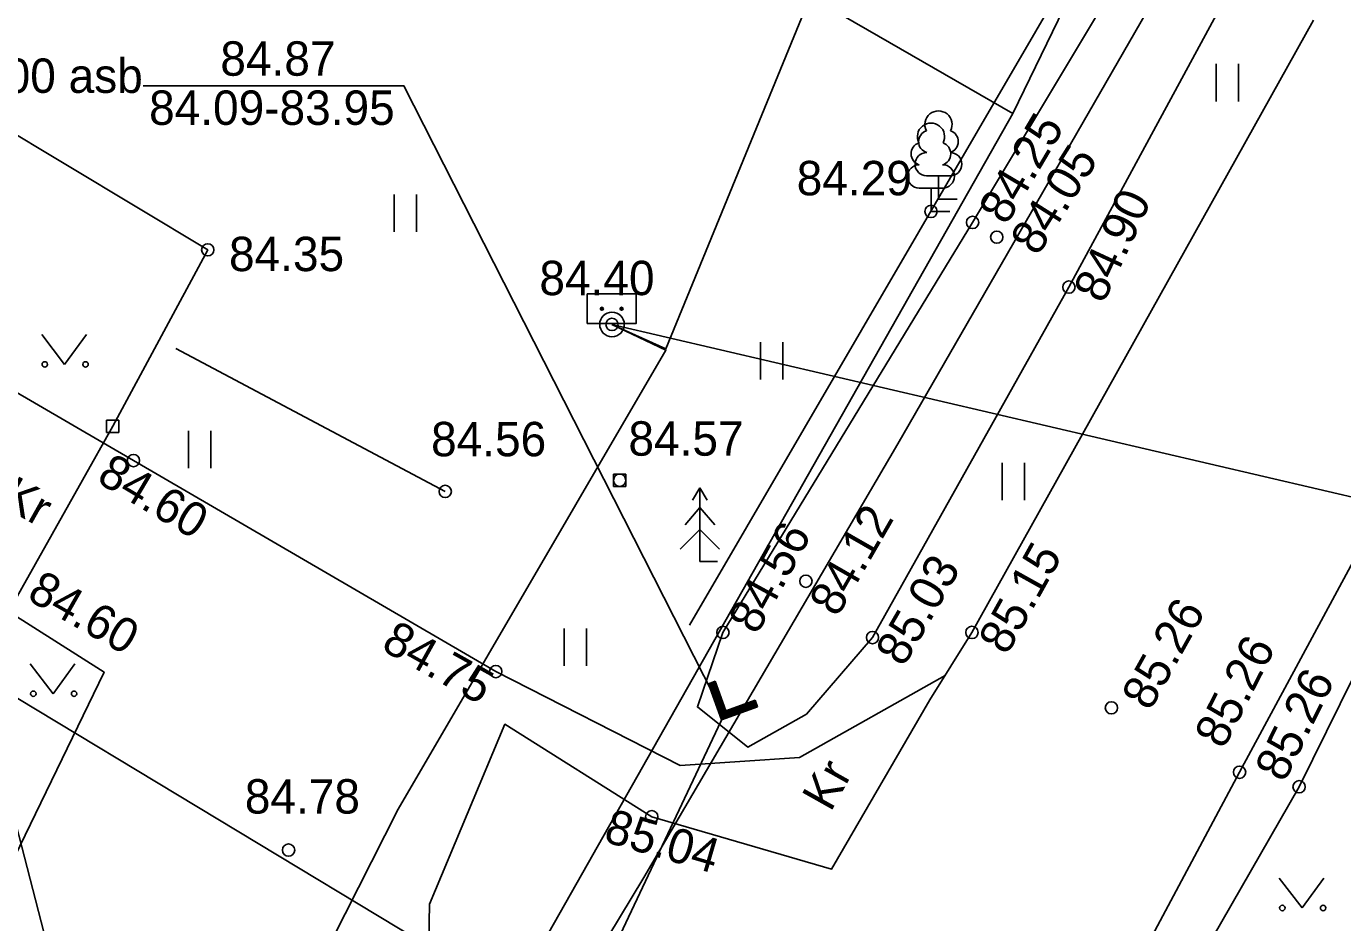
# Model space of a CAD drawing. Extents: x 648748 to 649126, y 6457789 to 6458252.
# Drawn here: x 648884.43 to 648911.21, y 6458173.84 to 6458192.08 of the extents above; entities that cross this region are included whole.
import ezdxf

# ---------------------------------------------------------------- set-up
doc = ezdxf.new("R2010")
doc.units = 0
for name, color, linetype in [('AED', 7, 'Continuous'), ('HALJASTUS', 7, 'Continuous'), ('KORGUS-EH2000', 7, 'Continuous'), ('KTRASS', 7, 'Continuous'), ('MPOHULIIN', 7, 'Continuous'), ('PIIR', 7, 'Continuous'), ('POST', 7, 'Continuous'), ('PUU', 7, 'Continuous'), ('SIOHULIIN', 7, 'Continuous'), ('SIRAJATIS', 7, 'Continuous'), ('SITRASS', 7, 'Continuous'), ('TEE', 7, 'Continuous'), ('TRUUP', 7, 'Continuous'), ('VEEKOGU', 7, 'Continuous')]:
    doc.layers.add(name, color=color, linetype=linetype)

msp = doc.modelspace()

# ---------------------------------------------------------------- linework, layer by layer
at = {"layer": 'AED'}
for p, q in [((648886.06, 6458184.069), (648886.06, 6458183.819)), ((648886.06, 6458184.069), (648886.31, 6458184.069)), ((648886.31, 6458184.069), (648886.31, 6458183.819)), ((648886.06, 6458183.819), (648886.31, 6458183.819)), ((648896.374, 6458182.97), (648896.374, 6458182.72)), ((648896.374, 6458182.97), (648896.624, 6458182.97)), ((648896.624, 6458182.97), (648896.624, 6458182.72)), ((648896.374, 6458182.72), (648896.624, 6458182.72))]:
    msp.add_line(p, q, dxfattribs=at)
msp.add_lwpolyline([(648883.709, 6458179.555), (648886.185, 6458183.944), (648888.119, 6458187.534), (648883.783, 6458190.14)], dxfattribs=at)
at = {"layer": 'HALJASTUS'}
for p, q in [((648908.637, 6458191.316), (648908.637, 6458190.555)), ((648909.092, 6458191.316), (648909.092, 6458190.555)), ((648891.91, 6458188.663), (648891.91, 6458187.902)), ((648892.365, 6458188.663), (648892.365, 6458187.902)), ((648884.741, 6458185.811), (648885.204, 6458185.204)), ((648885.204, 6458185.204), (648885.65, 6458185.811)), ((648892.951, 6458182.619), (648887.471, 6458185.525)), ((648899.366, 6458185.659), (648899.366, 6458184.898)), ((648899.821, 6458185.659), (648899.821, 6458184.898)), ((648887.727, 6458183.855), (648887.727, 6458183.094)), ((648888.182, 6458183.855), (648888.182, 6458183.094)), ((648904.281, 6458183.199), (648904.281, 6458182.438)), ((648904.736, 6458183.199), (648904.736, 6458182.438)), ((648895.368, 6458179.832), (648895.368, 6458179.071)), ((648895.823, 6458179.832), (648895.823, 6458179.071)), ((648884.508, 6458179.11), (648884.971, 6458178.503)), ((648884.971, 6458178.503), (648885.417, 6458179.11)), ((648909.918, 6458174.75), (648910.382, 6458174.143)), ((648910.382, 6458174.143), (648910.827, 6458174.75))]:
    msp.add_line(p, q, dxfattribs=at)
msp.add_lwpolyline([(648914.508, 6458217.558), (648916.03, 6458214.515), (648914.704, 6458209.998), (648909.63, 6458199.994), (648897.923, 6458179.895)], dxfattribs=at)
for centre in [(648884.803, 6458185.204), (648885.632, 6458185.204), (648884.57, 6458178.503), (648885.399, 6458178.503), (648909.981, 6458174.143), (648910.81, 6458174.143)]:
    msp.add_circle(centre, 0.055, dxfattribs=at)
at = {"layer": 'KORGUS-EH2000'}
for centre in [(648902.833, 6458188.317), (648903.68, 6458188.093), (648904.171, 6458187.792), (648888.119, 6458187.534), (648905.64, 6458186.776), (648896.343, 6458186.017), (648886.607, 6458183.247), (648896.499, 6458182.845), (648892.951, 6458182.619), (648900.287, 6458180.792), (648898.6, 6458179.75), (648901.643, 6458179.646), (648903.667, 6458179.751), (648893.979, 6458178.952), (648906.503, 6458178.216), (648909.112, 6458176.906), (648910.322, 6458176.61), (648897.151, 6458176.001), (648889.763, 6458175.322)]:
    msp.add_circle(centre, 0.125, dxfattribs=at)
at = {"layer": 'KTRASS'}
msp.add_line((648918.483, 6458157.779), (648878.199, 6458182.051), dxfattribs=at)
at = {"layer": 'MPOHULIIN'}
msp.add_lwpolyline([(648879.733, 6458193.241), (648887.677, 6458162.414), (648896.676, 6458127.492), (648901.112, 6458110.279), (648910.288, 6458074.678)], dxfattribs=at)
at = {"layer": 'PIIR'}
for p, q in [((648919.27, 6458220.73), (648904.5, 6458190.31)), ((648882.169, 6458203.173), (648904.5, 6458190.31)), ((648904.5, 6458190.31), (648875.65, 6458139.39))]:
    msp.add_line(p, q, dxfattribs=at)
at = {"layer": 'POST'}
msp.add_circle((648896.343, 6458186.017), 0.25, dxfattribs=at)
at = {"layer": 'PUU'}
for p, q in [((648903.224, 6458189.039), (648902.744, 6458189.039)), ((648902.984, 6458188.564), (648902.984, 6458189.039)), ((648903.073, 6458188.792), (648902.593, 6458188.792)), ((648902.833, 6458188.317), (648902.833, 6458188.792)), ((648903.364, 6458188.564), (648902.984, 6458188.564)), ((648903.213, 6458188.317), (648902.833, 6458188.317)), ((648898.132, 6458182.691), (648897.982, 6458182.441)), ((648898.282, 6458182.441), (648898.132, 6458182.691)), ((648898.132, 6458182.691), (648898.132, 6458181.191)), ((648898.132, 6458182.291), (648897.832, 6458181.941)), ((648898.432, 6458181.941), (648898.132, 6458182.291)), ((648898.132, 6458181.841), (648897.732, 6458181.441)), ((648898.532, 6458181.441), (648898.132, 6458181.841)), ((648898.492, 6458181.191), (648898.132, 6458181.191))]:
    msp.add_line(p, q, dxfattribs=at)
for centre, radius, start, end in [((648902.984, 6458190.084), 0.277, 332.58, 207.42), ((648902.833, 6458189.837), 0.277, 332.58, 207.42), ((648902.814, 6458189.737), 0.233, 109.022, 253.142), ((648903.154, 6458189.737), 0.233, 286.851, 70.986), ((648902.662, 6458189.489), 0.233, 109.022, 253.142), ((648903.003, 6458189.489), 0.233, 286.851, 70.986), ((648902.747, 6458189.277), 0.238, 90.002, 269.395), ((648903.222, 6458189.277), 0.238, 270.605, 89.998), ((648902.595, 6458189.029), 0.238, 90.002, 269.395), ((648903.07, 6458189.029), 0.238, 270.605, 89.998)]:
    msp.add_arc(centre, radius, start, end, dxfattribs=at)
at = {"layer": 'SIOHULIIN'}
msp.add_line((648896.343, 6458186.017), (648938.076, 6458176.279), dxfattribs=at)
at = {"layer": 'SIRAJATIS'}
msp.add_lwpolyline([(648895.838, 6458186.636), (648896.838, 6458186.636), (648896.838, 6458186.036), (648895.838, 6458186.036)], close=True, dxfattribs=at)
for centre, radius in [((648896.138, 6458186.336), 0.0304), ((648896.138, 6458186.336), 0.029), ((648896.138, 6458186.336), 0.0277), ((648896.138, 6458186.336), 0.0263), ((648896.138, 6458186.336), 0.0249), ((648896.138, 6458186.336), 0.0236), ((648896.138, 6458186.336), 0.0222), ((648896.138, 6458186.336), 0.0209), ((648896.138, 6458186.336), 0.0195), ((648896.138, 6458186.336), 0.0181), ((648896.138, 6458186.336), 0.0168), ((648896.138, 6458186.336), 0.0154), ((648896.138, 6458186.336), 0.014), ((648896.138, 6458186.336), 0.0127), ((648896.138, 6458186.336), 0.0113), ((648896.138, 6458186.336), 0.00996), ((648896.138, 6458186.336), 0.0086), ((648896.138, 6458186.336), 0.00724), ((648896.138, 6458186.336), 0.00587), ((648896.138, 6458186.336), 0.00451), ((648896.138, 6458186.336), 0.00315), ((648896.138, 6458186.336), 0.00179), ((648896.138, 6458186.336), 0.000426), ((648896.538, 6458186.336), 0.0304), ((648896.538, 6458186.336), 0.029), ((648896.538, 6458186.336), 0.0277), ((648896.538, 6458186.336), 0.0263), ((648896.538, 6458186.336), 0.0249), ((648896.538, 6458186.336), 0.0236), ((648896.538, 6458186.336), 0.0222), ((648896.538, 6458186.336), 0.0209), ((648896.538, 6458186.336), 0.0195), ((648896.538, 6458186.336), 0.0181), ((648896.538, 6458186.336), 0.0168), ((648896.538, 6458186.336), 0.0154), ((648896.538, 6458186.336), 0.014), ((648896.538, 6458186.336), 0.0127), ((648896.538, 6458186.336), 0.0113), ((648896.538, 6458186.336), 0.00996), ((648896.538, 6458186.336), 0.0086), ((648896.538, 6458186.336), 0.00724), ((648896.538, 6458186.336), 0.00587), ((648896.538, 6458186.336), 0.00451), ((648896.538, 6458186.336), 0.00315), ((648896.538, 6458186.336), 0.00179), ((648896.538, 6458186.336), 0.000426)]:
    msp.add_circle(centre, radius, dxfattribs=at)
at = {"layer": 'SITRASS'}
for points in [[(648929.925, 6458240.085), (648929.233, 6458238.833), (648926.729, 6458233.327), (648923.21, 6458225.506), (648918.966, 6458215.361), (648917.027, 6458210.342), (648911.341, 6458199.533), (648902.157, 6458183.584), (648896.992, 6458174.764), (648890.118, 6458163.377), (648888.523, 6458160), (648880.878, 6458146.779), (648876.372, 6458138.998), (648873.186, 6458136.533), (648872.398, 6458135.159), (648870.194, 6458131.921), (648868.778, 6458129.583), (648863.975, 6458121.708)], [(648920.046, 6458238.741), (648918.974, 6458235.501), (648918.374, 6458231.362), (648916.343, 6458227.563), (648914.757, 6458225.445), (648913.89, 6458223.662), (648910.648, 6458217.515), (648906.266, 6458207.122), (648902.537, 6458197.956), (648897.439, 6458185.518), (648896.343, 6458186.017)], [(648896.343, 6458186.017), (648897.439, 6458185.494), (648891.994, 6458176.157), (648887.134, 6458166.562), (648880.865, 6458155.928), (648874.577, 6458143.726), (648870.442, 6458134.893), (648860.973, 6458120.207), (648854.483, 6458107.787), (648851.762, 6458098.853), (648850.917, 6458095.378), (648847.878, 6458090.581), (648844.467, 6458087.013), (648842.522, 6458085.072), (648840.521, 6458082.239)]]:
    msp.add_lwpolyline(points, dxfattribs=at)
at = {"layer": 'TEE'}
for points in [[(648891.319, 6458123.494), (648901.175, 6458127.077), (648933.887, 6458139.607), (648944.575, 6458143.741), (648947.822, 6458145.717), (648948.882, 6458147.636), (648949.478, 6458151.73), (648949.531, 6458156.617), (648950.372, 6458161.859), (648951.909, 6458167.68), (648954.505, 6458172.94), (648956.528, 6458180.218), (648952.525, 6458185.448), (648945.526, 6458192.898), (648938.29, 6458202.321), (648932.248, 6458208.399), (648929.676, 6458210.569), (648928.257, 6458209.969), (648926.047, 6458207.531), (648924.786, 6458206.368), (648922.091, 6458200.973), (648909.112, 6458176.906), (648898.467, 6458156.964), (648883.402, 6458130.595)], [(648902.496, 6458156.185), (648903.183, 6458160.572), (648904.191, 6458165.567), (648906.598, 6458170.127), (648910.322, 6458176.61), (648916.438, 6458188.99), (648922.963, 6458200.444), (648925.76, 6458205.755), (648928.587, 6458207.759), (648932.657, 6458207.561), (648933.376, 6458207.264)], [(648910.613, 6458192.21), (648903.667, 6458179.751), (648902.811, 6458178.379), (648900.807, 6458174.931), (648897.151, 6458176.001), (648894.164, 6458177.881), (648892.628, 6458174.223), (648892.59, 6458172.02), (648894.122, 6458172.629), (648896.444, 6458172.027), (648898.105, 6458170.013), (648896.987, 6458167.363), (648892.71, 6458159.787), (648886.897, 6458149.241), (648880.501, 6458138.274)], [(648878.335, 6458188.065), (648886.607, 6458183.247), (648893.979, 6458178.952), (648897.729, 6458177.041), (648900.156, 6458177.208), (648903.119, 6458178.872)], [(648881.716, 6458175.368), (648883.753, 6458174.295), (648886.01, 6458178.942), (648884.077, 6458180.168), (648876.337, 6458185.071)]]:
    msp.add_lwpolyline(points, dxfattribs=at)
at = {"layer": 'TRUUP'}
for p, q in [((648898.443, 6458178.755), (648898.309, 6458178.706)), ((648898.309, 6458178.706), (648898.572, 6458177.974)), ((648898.337, 6458178.716), (648898.329, 6458178.651)), ((648898.363, 6458178.726), (648898.347, 6458178.599)), ((648898.389, 6458178.735), (648898.366, 6458178.547)), ((648898.376, 6458178.73), (648898.615, 6458178.065)), ((648898.416, 6458178.745), (648898.385, 6458178.495)), ((648898.442, 6458178.754), (648898.404, 6458178.443)), ((648898.461, 6458178.704), (648898.423, 6458178.39)), ((648898.48, 6458178.652), (648898.441, 6458178.338)), ((648898.443, 6458178.755), (648898.658, 6458178.156)), ((648898.499, 6458178.599), (648898.46, 6458178.285)), ((648898.517, 6458178.547), (648898.479, 6458178.233)), ((648898.536, 6458178.495), (648898.498, 6458178.181)), ((648898.555, 6458178.443), (648898.516, 6458178.129)), ((648898.574, 6458178.391), (648898.535, 6458178.076)), ((648898.592, 6458178.338), (648898.554, 6458178.024)), ((648898.615, 6458178.065), (648899.28, 6458178.304)), ((648898.658, 6458178.156), (648899.256, 6458178.371)), ((648899.04, 6458178.293), (648899.021, 6458178.135)), ((648899.067, 6458178.303), (648899.047, 6458178.145)), ((648899.093, 6458178.312), (648899.074, 6458178.154)), ((648899.12, 6458178.322), (648899.1, 6458178.163)), ((648899.146, 6458178.331), (648899.126, 6458178.173)), ((648899.172, 6458178.341), (648899.153, 6458178.182)), ((648899.198, 6458178.35), (648899.179, 6458178.192)), ((648899.225, 6458178.359), (648899.205, 6458178.201)), ((648899.251, 6458178.369), (648899.232, 6458178.211)), ((648899.256, 6458178.371), (648899.305, 6458178.237)), ((648899.271, 6458178.329), (648899.258, 6458178.22)), ((648898.615, 6458178.065), (648895.215, 6458170.857)), ((648898.572, 6458177.974), (648899.305, 6458178.237)), ((648898.611, 6458178.286), (648898.573, 6458177.974)), ((648898.63, 6458178.233), (648898.599, 6458177.984)), ((648898.649, 6458178.181), (648898.626, 6458177.993)), ((648898.671, 6458178.161), (648898.652, 6458178.003)), ((648898.698, 6458178.17), (648898.679, 6458178.012)), ((648898.724, 6458178.18), (648898.705, 6458178.021)), ((648898.75, 6458178.189), (648898.731, 6458178.031)), ((648898.777, 6458178.199), (648898.757, 6458178.04)), ((648898.803, 6458178.208), (648898.784, 6458178.05)), ((648898.829, 6458178.217), (648898.81, 6458178.06)), ((648898.856, 6458178.227), (648898.836, 6458178.069)), ((648898.882, 6458178.237), (648898.863, 6458178.078)), ((648898.909, 6458178.246), (648898.889, 6458178.088)), ((648898.935, 6458178.256), (648898.915, 6458178.097)), ((648898.961, 6458178.265), (648898.942, 6458178.107)), ((648898.988, 6458178.274), (648898.968, 6458178.116)), ((648899.014, 6458178.284), (648898.995, 6458178.126)), ((648899.29, 6458178.277), (648899.285, 6458178.229))]:
    msp.add_line(p, q, dxfattribs=at)
msp.add_lwpolyline([(648886.805, 6458190.868), (648892.11, 6458190.868), (648898.615, 6458178.065)], dxfattribs=at)
at = {"layer": 'VEEKOGU'}
msp.add_lwpolyline([(648908.824, 6458196.674), (648903.68, 6458188.093), (648898.6, 6458179.75), (648898.082, 6458178.233), (648899.104, 6458177.418), (648900.301, 6458178.087), (648901.643, 6458179.646), (648905.64, 6458186.776), (648910.629, 6458195.996)], dxfattribs=at)

# ---------------------------------------------------------------- texts
at = {"layer": 'KORGUS-EH2000'}
for s, rotation, p in [('84.25', 59.3728, (648904.367, 6458188.014)), ('84.05', 57.7244, (648905.001, 6458187.386)), ('84.90', 65.0754, (648906.34, 6458186.42)), ('84.60', 329.32, (648885.83, 6458182.824)), ('84.12', 60.1446, (648900.927, 6458180.04)), ('84.56', 61.3678, (648899.29, 6458179.681)), ('85.15', 60.8613, (648904.376, 6458179.265)), ('85.03', 59.9429, (648902.275, 6458179.026)), ('84.60', 330.3528, (648884.412, 6458180.435)), ('85.26', 60.8613, (648907.288, 6458178.131)), ('84.75', 330.7027, (648891.62, 6458179.412)), ('85.26', 62.8833, (648908.786, 6458177.355)), ('85.26', 63.7102, (648910.021, 6458176.676)), ('85.04', 343.6883, (648896.148, 6458175.502))]:
    msp.add_text(s, height=0.7, rotation=rotation, dxfattribs=at).set_placement(p)
for s, p in [('84.29', (648900.101, 6458188.644)), ('84.35', (648888.551, 6458187.101)), ('84.40', (648894.866, 6458186.612)), ('84.56', (648892.662, 6458183.334)), ('84.57', (648896.677, 6458183.346)), ('84.78', (648888.873, 6458176.064))]:
    msp.add_text(s, height=0.7, dxfattribs=at).set_placement(p)
at = {"layer": 'TEE'}
for rotation, p in [(330.6422, (648883.874, 6458182.346)), (60.6422, (648900.79, 6458176.079))]:
    msp.add_text('Kr', height=0.7, rotation=rotation, dxfattribs=at).set_placement(p)
at = {"layer": 'TRUUP'}
for s, p in [('84.87', (648888.375, 6458191.077)), ('DN300 asb', (648882.114, 6458190.728)), ('84.09-83.95', (648886.925, 6458190.077))]:
    msp.add_text(s, height=0.7, dxfattribs=at).set_placement(p)

doc.saveas('drawing.dxf')
